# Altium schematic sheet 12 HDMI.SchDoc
size 246 x 182 mm
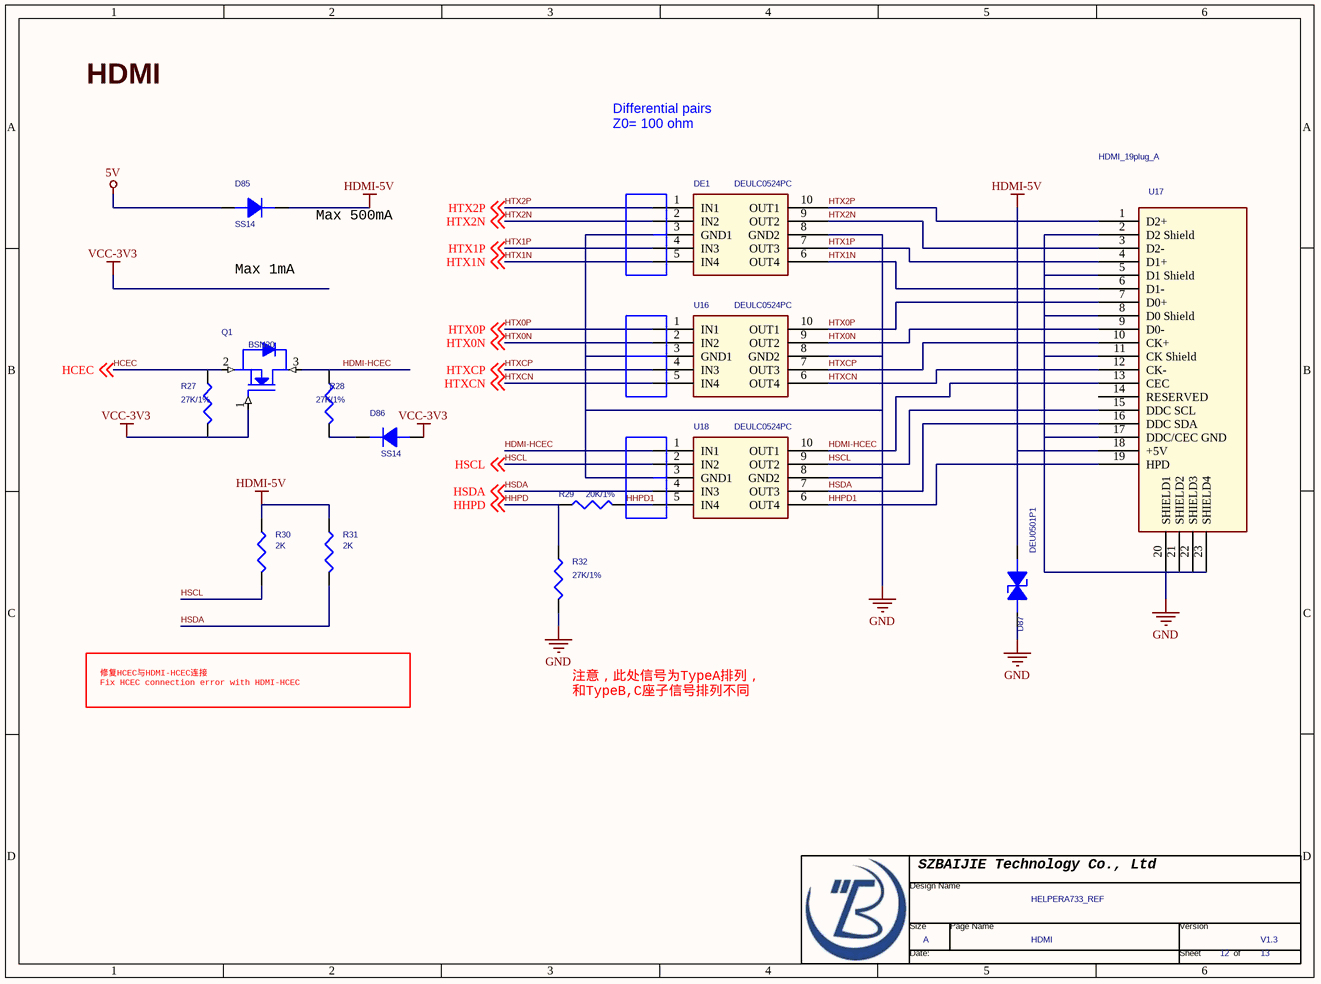
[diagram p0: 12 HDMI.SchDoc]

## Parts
*  Page Count: 13  Page Number: 12  Page Size: A  Title: HELPERA733_REF  RevCode: V1.3  Doc: HDMI  (hidden comment: TitleBlock0-BJ)  (graphical)
D85  SS14  [SOD123]
D86  SS14  [SOD123]
D87  DEU0501P1  [ESD0402]
DE1  DEULC0524PC  [DFN2510-10_L2.5-W1.0-P0.50-BL]
Q1  BSN20  [sot-23]
R27  27K/1%  [R0402]
R28  27K/1%  [R0402]
R29  20K/1%  [R0402]
R30  2K  [R0402]
R31  2K  [R0402]
R32  27K/1%  [R0402]
U16  DEULC0524PC  [DFN2510-10_L2.5-W1.0-P0.50-BL]
U17  HDMI_19plug_A  [HDMIQ]
U18  DEULC0524PC  [DFN2510-10_L2.5-W1.0-P0.50-BL]

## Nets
5V: D85.1
GND: D87.2(CATHODE) DE1.3(GND1) DE1.8(GND2) R32.2 U16.3(GND1) U16.8(GND2) U17.2(D2_Shield) U17.5(D1_Shield) U17.8(D0_Shield) U17.11(CK_Shield) U17.17(DDC/CEC_GND) U17.20(SHIELD1) U17.21(SHIELD2) U17.22(SHIELD3) U17.23(SHIELD4) U18.3(GND1) U18.8(GND2)
HDMI-5V: D85.2 D87.1(ANODE) R30.2 R31.2 U17.18(+5V)
VCC-3V3: D86.1 Q1.1(GATE) R27.2
HCEC: Q1.2(SOURCE) R27.1 ; off-sheet HCEC
HDMI-HCEC: Q1.3(DRAIN) R28.2 U17.13(CEC) U18.1(IN1) U18.10(OUT1)
HHPD: R29.1 R32.1 ; off-sheet HHPD
HHPD1: R29.2 U17.19(HPD) U18.5(IN4) U18.6(OUT4)
HSCL: R30.1 U17.15(DDC_SCL) U18.2(IN2) U18.9(OUT2) ; off-sheet HSCL
HSDA: R31.1 U17.16(DDC_SDA) U18.4(IN3) U18.7(OUT3) ; off-sheet HSDA
HTX0N: U16.2(IN2) U16.9(OUT2) U17.9(D0-) ; off-sheet HTX0N
HTX0P: U16.1(IN1) U16.10(OUT1) U17.7(D0+) ; off-sheet HTX0P
HTX1N: DE1.5(IN4) DE1.6(OUT4) U17.6(D1-) ; off-sheet HTX1N
HTX1P: DE1.4(IN3) DE1.7(OUT3) U17.4(D1+) ; off-sheet HTX1P
HTX2N: DE1.2(IN2) DE1.9(OUT2) U17.3(D2-) ; off-sheet HTX2N
HTX2P: DE1.1(IN1) DE1.10(OUT1) U17.1(D2+) ; off-sheet HTX2P
HTXCN: U16.5(IN4) U16.6(OUT4) U17.12(CK-) ; off-sheet HTXCN
HTXCP: U16.4(IN3) U16.7(OUT3) U17.10(CK+) ; off-sheet HTXCP
NetD86_2: D86.2 R28.1

Not connected (* = marked no-connect by the designer): U17 14(RESERVED)

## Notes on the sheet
- HDMI
- Differential pairs
  Z0= 100 ohm
- (near D85) Max 500mA
- Max 1mA
- 修复HCEC与HDMI-HCEC连接
  Fix HCEC connection error with HDMI-HCEC
- 注意，此处信号为TypeA排列，
  和TypeB,C座子信号排列不同

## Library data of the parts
D85 D86 = D_0: Allegro PCB Footprint: d2513A
D87 = 1_1.5KE100A: 1ST PART DESCRIPTION: WILL ESD9B5V Bidirection ESD Protection
DE1 U16 U18 = rRClamp0524P
Q1 = NMOS_0
R27 R28 R32 = RESISTOR_Dup3
R29 = R_Dup1
R30 R31 = RESISTOR_Dup2
U17 = HDMI_A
